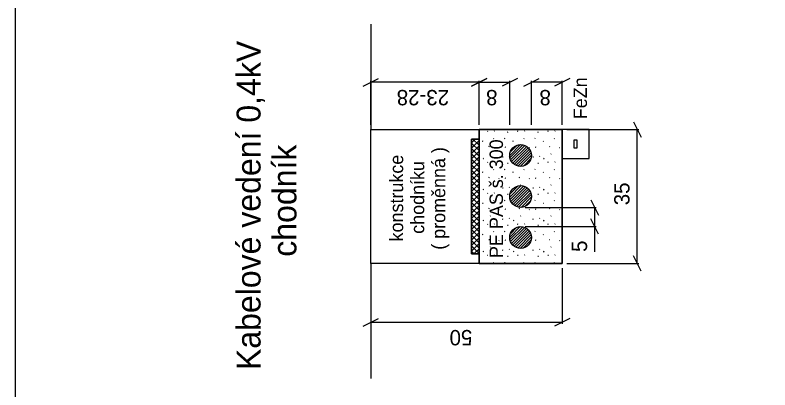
# Model space of a CAD drawing. Extents: x -762592 to -762444, y -1032635 to -1032425.
# Drawn here: x -762592.03 to -762560.49, y -1032580.78 to -1032565.13 of the extents above; entities that cross this region are included whole.
import ezdxf

# ---------------------------------------------------------------- set-up
doc = ezdxf.new("R2010")
doc.units = 0
for name, color, linetype in [('Chráničky - koruflex', 7, 'Continuous'), ('Kabeláž - kabelové vedení HDV - stávající', 7, 'Continuous'), ('Tisk', 7, 'Continuous'), ('X ŘEZY TRASOU', 7, 'Continuous'), ('X ŘEZY TRASOU - KÓTY', 7, 'Continuous'), ('X ŘEZY TRASOU - ŠRAFY', 7, 'Continuous')]:
    doc.layers.add(name, color=color, linetype=linetype)

msp = doc.modelspace()

# ---------------------------------------------------------------- linework, layer by layer
at = {"layer": 'Kabeláž - kabelové vedení HDV - stávající'}
for p, q in [((-762571.36, -1032570.986), (-762570.911, -1032570.538)), ((-762571.349, -1032571.089), (-762570.809, -1032570.548)), ((-762571.336, -1032570.85), (-762571.048, -1032570.562)), ((-762571.323, -1032571.175), (-762570.723, -1032570.576)), ((-762571.282, -1032571.248), (-762570.65, -1032570.616)), ((-762571.231, -1032571.31), (-762570.588, -1032570.667)), ((-762571.171, -1032571.363), (-762570.535, -1032570.728)), ((-762571.099, -1032571.405), (-762570.493, -1032570.798)), ((-762571.016, -1032571.435), (-762570.463, -1032570.882)), ((-762570.917, -1032571.448), (-762570.45, -1032570.981)), ((-762570.789, -1032571.433), (-762570.465, -1032571.109)), ((-762571.359, -1032572.729), (-762570.881, -1032572.25)), ((-762571.349, -1032572.605), (-762571.005, -1032572.262)), ((-762571.344, -1032572.826), (-762570.784, -1032572.267)), ((-762571.312, -1032572.908), (-762570.702, -1032572.297)), ((-762571.269, -1032572.978), (-762570.632, -1032572.341)), ((-762571.216, -1032573.038), (-762570.572, -1032572.394)), ((-762571.152, -1032573.087), (-762570.522, -1032572.457)), ((-762571.078, -1032573.126), (-762570.484, -1032572.532)), ((-762570.991, -1032573.152), (-762570.457, -1032572.618)), ((-762570.886, -1032573.161), (-762570.45, -1032572.724)), ((-762570.743, -1032573.131), (-762570.478, -1032572.866)), ((-762571.36, -1032574.4), (-762570.921, -1032573.962)), ((-762571.352, -1032574.506), (-762570.817, -1032573.971)), ((-762571.332, -1032574.259), (-762571.064, -1032573.991)), ((-762571.325, -1032574.592), (-762570.73, -1032573.997)), ((-762571.286, -1032574.666), (-762570.656, -1032574.036)), ((-762571.236, -1032574.729), (-762570.592, -1032574.085)), ((-762571.176, -1032574.782), (-762570.54, -1032574.146)), ((-762571.107, -1032574.826), (-762570.497, -1032574.216)), ((-762571.024, -1032574.857), (-762570.465, -1032574.298)), ((-762570.927, -1032574.873), (-762570.45, -1032574.396)), ((-762570.802, -1032574.861), (-762570.461, -1032574.52))]:
    msp.add_line(p, q, dxfattribs=at)
at = {"layer": 'Tisk'}
msp.add_lwpolyline([(-762589.528, -1032529.685), (-762592.028, -1032529.685), (-762592.028, -1032634.685), (-762443.528, -1032634.685), (-762443.528, -1032529.685), (-762446.028, -1032529.685)], dxfattribs=at)
at = {"layer": 'X ŘEZY TRASOU'}
for p, q in [((-762577.169, -1032565.505), (-762577.169, -1032569.905)), ((-762572.641, -1032569.905), (-762572.641, -1032575.505)), ((-762572.961, -1032570.459), (-762572.807, -1032570.305)), ((-762572.961, -1032570.685), (-762572.641, -1032570.365)), ((-762572.641, -1032570.791), (-762572.961, -1032570.471)), ((-762572.641, -1032570.564), (-762572.9, -1032570.305)), ((-762572.641, -1032570.338), (-762572.673, -1032570.305)), ((-762572.961, -1032570.912), (-762572.641, -1032570.592)), ((-762572.641, -1032571.017), (-762572.961, -1032570.697)), ((-762572.961, -1032571.138), (-762572.641, -1032570.818)), ((-762572.641, -1032571.243), (-762572.961, -1032570.923)), ((-762572.961, -1032571.364), (-762572.641, -1032571.044)), ((-762572.641, -1032571.47), (-762572.961, -1032571.15)), ((-762572.961, -1032571.59), (-762572.641, -1032571.27)), ((-762572.641, -1032571.696), (-762572.961, -1032571.376)), ((-762572.961, -1032571.817), (-762572.641, -1032571.497)), ((-762572.641, -1032571.922), (-762572.961, -1032571.602)), ((-762572.961, -1032572.043), (-762572.641, -1032571.723)), ((-762572.641, -1032572.148), (-762572.961, -1032571.828)), ((-762572.961, -1032572.269), (-762572.641, -1032571.949)), ((-762572.641, -1032572.375), (-762572.961, -1032572.055)), ((-762572.961, -1032572.495), (-762572.641, -1032572.175)), ((-762572.641, -1032572.601), (-762572.961, -1032572.281)), ((-762572.961, -1032572.722), (-762572.641, -1032572.402)), ((-762572.641, -1032572.827), (-762572.961, -1032572.507)), ((-762572.961, -1032572.948), (-762572.641, -1032572.628)), ((-762572.641, -1032573.053), (-762572.961, -1032572.733)), ((-762572.961, -1032573.174), (-762572.641, -1032572.854)), ((-762572.641, -1032573.28), (-762572.961, -1032572.96)), ((-762572.961, -1032573.401), (-762572.641, -1032573.081)), ((-762572.641, -1032573.506), (-762572.961, -1032573.186)), ((-762572.961, -1032573.627), (-762572.641, -1032573.307)), ((-762572.641, -1032573.732), (-762572.961, -1032573.412)), ((-762572.961, -1032573.853), (-762572.641, -1032573.533)), ((-762572.641, -1032573.959), (-762572.961, -1032573.639)), ((-762572.961, -1032574.079), (-762572.641, -1032573.759)), ((-762572.641, -1032574.185), (-762572.961, -1032573.865)), ((-762572.961, -1032574.306), (-762572.641, -1032573.986)), ((-762572.641, -1032574.411), (-762572.961, -1032574.091)), ((-762572.961, -1032574.532), (-762572.641, -1032574.212)), ((-762572.641, -1032574.637), (-762572.961, -1032574.317)), ((-762572.961, -1032574.758), (-762572.641, -1032574.438)), ((-762572.641, -1032574.864), (-762572.961, -1032574.544)), ((-762572.961, -1032574.984), (-762572.641, -1032574.664)), ((-762572.641, -1032575.09), (-762572.961, -1032574.77)), ((-762572.855, -1032575.105), (-762572.641, -1032574.891)), ((-762572.851, -1032575.105), (-762572.961, -1032574.996)), ((-762577.169, -1032575.505), (-762577.169, -1032580.305)), ((-762577.169, -1032577.105), (-762577.169, -1032579.4))]:
    msp.add_line(p, q, dxfattribs=at)
for points in [[(-762577.169, -1032575.505), (-762577.169, -1032569.905), (-762572.641, -1032569.905), (-762572.641, -1032575.505)], [(-762572.641, -1032575.505), (-762572.641, -1032569.905), (-762569.169, -1032569.905), (-762569.169, -1032575.505)], [(-762569.169, -1032569.905), (-762569.169, -1032571.115), (-762568.047, -1032571.115), (-762568.047, -1032569.905)], [(-762572.961, -1032575.105), (-762572.961, -1032570.305), (-762572.641, -1032570.305), (-762572.641, -1032575.105)], [(-762568.663, -1032570.681), (-762568.663, -1032570.339), (-762568.552, -1032570.339), (-762568.552, -1032570.681)]]:
    msp.add_lwpolyline(points, close=True, dxfattribs=at)
msp.add_lwpolyline([(-762572.641, -1032575.105), (-762572.641, -1032570.305), (-762572.961, -1032570.305), (-762572.961, -1032575.105), (-762572.641, -1032575.105)], dxfattribs=at)
for centre in [(-762570.905, -1032570.993), (-762570.905, -1032572.705), (-762570.905, -1032574.417)]:
    msp.add_circle(centre, 0.456, dxfattribs=at)
at = {"layer": 'X ŘEZY TRASOU - KÓTY'}
for p, q in [((-762577.489, -1032568.096), (-762576.849, -1032567.776)), ((-762577.169, -1032569.713), (-762577.169, -1032567.872)), ((-762572.641, -1032567.936), (-762577.169, -1032567.936)), ((-762572.961, -1032568.096), (-762572.321, -1032567.776)), ((-762572.321, -1032567.776), (-762572.961, -1032568.096)), ((-762572.641, -1032569.713), (-762572.641, -1032567.872)), ((-762572.641, -1032569.713), (-762572.641, -1032567.872)), ((-762572.641, -1032567.936), (-762571.361, -1032567.936)), ((-762571.041, -1032567.776), (-762571.681, -1032568.096)), ((-762571.361, -1032569.713), (-762571.361, -1032567.872)), ((-762570.769, -1032568.096), (-762570.129, -1032567.776)), ((-762570.449, -1032569.713), (-762570.449, -1032567.872)), ((-762569.169, -1032567.936), (-762570.449, -1032567.936)), ((-762568.849, -1032567.776), (-762569.489, -1032568.096)), ((-762569.169, -1032569.713), (-762569.169, -1032567.872)), ((-762566.194, -1032569.585), (-762565.874, -1032570.225)), ((-762568.977, -1032569.905), (-762565.97, -1032569.905)), ((-762566.034, -1032575.505), (-762566.034, -1032569.905)), ((-762567.967, -1032572.841), (-762567.647, -1032573.481)), ((-762570.713, -1032573.161), (-762567.743, -1032573.161)), ((-762567.807, -1032573.961), (-762567.807, -1032573.161)), ((-762567.647, -1032574.281), (-762567.967, -1032573.641)), ((-762570.713, -1032573.961), (-762567.743, -1032573.961)), ((-762567.807, -1032575.022), (-762567.807, -1032573.961)), ((-762565.874, -1032575.825), (-762566.194, -1032575.185)), ((-762568.977, -1032575.505), (-762565.97, -1032575.505)), ((-762577.169, -1032575.697), (-762577.169, -1032578.026)), ((-762569.169, -1032575.697), (-762569.169, -1032578.026)), ((-762577.489, -1032578.122), (-762576.849, -1032577.802)), ((-762568.849, -1032577.802), (-762569.489, -1032578.122)), ((-762569.169, -1032577.962), (-762577.169, -1032577.962))]:
    msp.add_line(p, q, dxfattribs=at)
at = {"layer": 'X ŘEZY TRASOU - ŠRAFY'}
for p, q in [((-762569.169, -1032569.905), (-762572.641, -1032569.905)), ((-762572.641, -1032569.905), (-762572.641, -1032570.305)), ((-762569.169, -1032571.115), (-762569.169, -1032569.905)), ((-762572.271, -1032569.987), (-762572.295, -1032569.976)), ((-762572.006, -1032569.971), (-762571.99, -1032569.96)), ((-762571.453, -1032570.012), (-762571.429, -1032570.01)), ((-762571.006, -1032569.987), (-762571.031, -1032569.976)), ((-762570.741, -1032569.971), (-762570.725, -1032569.96)), ((-762570.188, -1032570.012), (-762570.164, -1032570.01)), ((-762569.742, -1032569.987), (-762569.766, -1032569.976)), ((-762569.477, -1032569.971), (-762569.461, -1032569.96)), ((-762572.641, -1032570.305), (-762572.641, -1032575.105)), ((-762572.472, -1032570.41), (-762572.496, -1032570.399)), ((-762572.035, -1032570.29), (-762572.019, -1032570.28)), ((-762571.573, -1032570.28), (-762571.557, -1032570.269)), ((-762571.207, -1032570.41), (-762571.231, -1032570.399)), ((-762570.771, -1032570.29), (-762570.754, -1032570.28)), ((-762570.309, -1032570.28), (-762570.293, -1032570.269)), ((-762569.942, -1032570.41), (-762569.967, -1032570.399)), ((-762569.506, -1032570.29), (-762569.49, -1032570.28)), ((-762572.208, -1032570.629), (-762572.233, -1032570.618)), ((-762571.814, -1032570.665), (-762571.797, -1032570.654)), ((-762571.521, -1032570.656), (-762571.545, -1032570.645)), ((-762570.549, -1032570.665), (-762570.533, -1032570.654)), ((-762570.256, -1032570.656), (-762570.281, -1032570.645)), ((-762569.679, -1032570.629), (-762569.704, -1032570.618)), ((-762569.285, -1032570.665), (-762569.268, -1032570.654)), ((-762572.641, -1032571.024), (-762572.63, -1032571.017)), ((-762572.471, -1032571.125), (-762572.455, -1032571.114)), ((-762572.465, -1032571.113), (-762572.449, -1032571.102)), ((-762572.177, -1032570.932), (-762572.161, -1032570.921)), ((-762571.632, -1032571.067), (-762571.656, -1032571.056)), ((-762571.381, -1032571.028), (-762571.365, -1032571.017)), ((-762570.367, -1032571.067), (-762570.392, -1032571.056)), ((-762570.117, -1032571.028), (-762570.1, -1032571.017)), ((-762569.942, -1032571.125), (-762569.926, -1032571.114)), ((-762569.936, -1032571.113), (-762569.92, -1032571.102)), ((-762569.648, -1032570.932), (-762569.631, -1032570.921)), ((-762572.271, -1032571.284), (-762572.295, -1032571.273)), ((-762572.006, -1032571.268), (-762571.99, -1032571.257)), ((-762571.453, -1032571.309), (-762571.429, -1032571.307)), ((-762570.188, -1032571.309), (-762570.164, -1032571.307)), ((-762569.742, -1032571.284), (-762569.766, -1032571.273)), ((-762569.477, -1032571.268), (-762569.461, -1032571.257)), ((-762572.472, -1032571.707), (-762572.496, -1032571.696)), ((-762572.035, -1032571.587), (-762572.019, -1032571.577)), ((-762571.573, -1032571.577), (-762571.557, -1032571.566)), ((-762571.207, -1032571.707), (-762571.231, -1032571.696)), ((-762570.771, -1032571.587), (-762570.754, -1032571.577)), ((-762570.309, -1032571.577), (-762570.293, -1032571.566)), ((-762569.942, -1032571.707), (-762569.967, -1032571.696)), ((-762569.506, -1032571.587), (-762569.49, -1032571.577)), ((-762572.208, -1032571.926), (-762572.233, -1032571.915)), ((-762571.814, -1032571.962), (-762571.797, -1032571.951)), ((-762571.521, -1032571.953), (-762571.545, -1032571.942)), ((-762570.944, -1032571.926), (-762570.968, -1032571.915)), ((-762570.549, -1032571.962), (-762570.533, -1032571.951)), ((-762570.256, -1032571.953), (-762570.281, -1032571.942)), ((-762569.679, -1032571.926), (-762569.704, -1032571.915)), ((-762569.285, -1032571.962), (-762569.268, -1032571.951)), ((-762572.641, -1032572.321), (-762572.63, -1032572.314)), ((-762572.471, -1032572.422), (-762572.455, -1032572.411)), ((-762572.465, -1032572.41), (-762572.449, -1032572.399)), ((-762572.177, -1032572.229), (-762572.161, -1032572.218)), ((-762571.632, -1032572.364), (-762571.656, -1032572.353)), ((-762571.381, -1032572.325), (-762571.365, -1032572.314)), ((-762570.912, -1032572.229), (-762570.896, -1032572.218)), ((-762570.367, -1032572.364), (-762570.392, -1032572.353)), ((-762570.117, -1032572.325), (-762570.1, -1032572.314)), ((-762569.942, -1032572.422), (-762569.926, -1032572.411)), ((-762569.936, -1032572.41), (-762569.92, -1032572.399)), ((-762569.648, -1032572.229), (-762569.631, -1032572.218)), ((-762572.271, -1032572.581), (-762572.295, -1032572.57)), ((-762572.006, -1032572.565), (-762571.99, -1032572.554)), ((-762571.453, -1032572.606), (-762571.429, -1032572.604)), ((-762570.188, -1032572.606), (-762570.164, -1032572.604)), ((-762569.742, -1032572.581), (-762569.766, -1032572.57)), ((-762569.477, -1032572.565), (-762569.461, -1032572.554)), ((-762572.472, -1032573.003), (-762572.496, -1032572.993)), ((-762572.035, -1032572.884), (-762572.019, -1032572.874)), ((-762571.573, -1032572.874), (-762571.557, -1032572.863)), ((-762570.309, -1032572.874), (-762570.293, -1032572.863)), ((-762569.942, -1032573.003), (-762569.967, -1032572.993)), ((-762569.506, -1032572.884), (-762569.49, -1032572.874)), ((-762572.208, -1032573.223), (-762572.233, -1032573.212)), ((-762571.814, -1032573.259), (-762571.797, -1032573.248)), ((-762571.521, -1032573.25), (-762571.545, -1032573.239)), ((-762570.944, -1032573.223), (-762570.968, -1032573.212)), ((-762570.549, -1032573.259), (-762570.533, -1032573.248)), ((-762570.256, -1032573.25), (-762570.281, -1032573.239)), ((-762569.679, -1032573.223), (-762569.704, -1032573.212)), ((-762569.285, -1032573.259), (-762569.268, -1032573.248)), ((-762572.641, -1032573.618), (-762572.63, -1032573.611)), ((-762572.471, -1032573.718), (-762572.455, -1032573.708)), ((-762572.465, -1032573.707), (-762572.449, -1032573.696)), ((-762572.177, -1032573.526), (-762572.161, -1032573.515)), ((-762571.632, -1032573.661), (-762571.656, -1032573.65)), ((-762571.381, -1032573.622), (-762571.365, -1032573.611)), ((-762571.207, -1032573.718), (-762571.191, -1032573.708)), ((-762571.201, -1032573.707), (-762571.184, -1032573.696)), ((-762570.912, -1032573.526), (-762570.896, -1032573.515)), ((-762570.367, -1032573.661), (-762570.392, -1032573.65)), ((-762570.117, -1032573.622), (-762570.1, -1032573.611)), ((-762569.942, -1032573.718), (-762569.926, -1032573.708)), ((-762569.936, -1032573.707), (-762569.92, -1032573.696)), ((-762569.648, -1032573.526), (-762569.631, -1032573.515)), ((-762572.271, -1032573.878), (-762572.295, -1032573.867)), ((-762572.006, -1032573.861), (-762571.99, -1032573.851)), ((-762571.453, -1032573.903), (-762571.429, -1032573.901)), ((-762571.006, -1032573.878), (-762571.031, -1032573.867)), ((-762570.741, -1032573.861), (-762570.725, -1032573.851)), ((-762570.188, -1032573.903), (-762570.164, -1032573.901)), ((-762569.742, -1032573.878), (-762569.766, -1032573.867)), ((-762569.477, -1032573.861), (-762569.461, -1032573.851)), ((-762572.472, -1032574.3), (-762572.496, -1032574.29)), ((-762572.035, -1032574.181), (-762572.019, -1032574.171)), ((-762571.573, -1032574.171), (-762571.557, -1032574.16)), ((-762570.309, -1032574.171), (-762570.293, -1032574.16)), ((-762569.942, -1032574.3), (-762569.967, -1032574.29)), ((-762569.506, -1032574.181), (-762569.49, -1032574.171)), ((-762572.208, -1032574.52), (-762572.233, -1032574.509)), ((-762571.814, -1032574.556), (-762571.797, -1032574.545)), ((-762571.521, -1032574.547), (-762571.545, -1032574.536)), ((-762570.256, -1032574.547), (-762570.281, -1032574.536)), ((-762569.679, -1032574.52), (-762569.704, -1032574.509)), ((-762569.285, -1032574.556), (-762569.268, -1032574.545)), ((-762572.641, -1032574.915), (-762572.63, -1032574.908)), ((-762572.177, -1032574.823), (-762572.161, -1032574.812)), ((-762571.632, -1032574.958), (-762571.656, -1032574.947)), ((-762571.381, -1032574.919), (-762571.365, -1032574.908)), ((-762570.367, -1032574.958), (-762570.392, -1032574.947)), ((-762570.117, -1032574.919), (-762570.1, -1032574.908)), ((-762569.648, -1032574.823), (-762569.631, -1032574.812)), ((-762572.471, -1032575.015), (-762572.455, -1032575.005)), ((-762572.465, -1032575.004), (-762572.449, -1032574.993)), ((-762572.271, -1032575.175), (-762572.295, -1032575.164)), ((-762572.006, -1032575.158), (-762571.99, -1032575.148)), ((-762571.453, -1032575.2), (-762571.429, -1032575.197)), ((-762571.207, -1032575.015), (-762571.191, -1032575.005)), ((-762571.201, -1032575.004), (-762571.184, -1032574.993)), ((-762571.006, -1032575.175), (-762571.031, -1032575.164)), ((-762570.741, -1032575.158), (-762570.725, -1032575.148)), ((-762570.188, -1032575.2), (-762570.164, -1032575.197)), ((-762569.942, -1032575.015), (-762569.926, -1032575.005)), ((-762569.936, -1032575.004), (-762569.92, -1032574.993)), ((-762569.742, -1032575.175), (-762569.766, -1032575.164)), ((-762569.477, -1032575.158), (-762569.461, -1032575.148)), ((-762572.035, -1032575.478), (-762572.019, -1032575.467)), ((-762571.573, -1032575.468), (-762571.557, -1032575.457)), ((-762570.771, -1032575.478), (-762570.754, -1032575.467)), ((-762570.309, -1032575.468), (-762570.293, -1032575.457)), ((-762569.506, -1032575.478), (-762569.49, -1032575.467))]:
    msp.add_line(p, q, dxfattribs=at)
msp.add_lwpolyline([(-762572.641, -1032575.105), (-762572.641, -1032575.505), (-762569.169, -1032575.505), (-762569.169, -1032571.115)], dxfattribs=at)
for centre in [(-762570.905, -1032570.993), (-762570.905, -1032572.705), (-762570.905, -1032574.417)]:
    msp.add_circle(centre, 0.456, dxfattribs=at)

# ---------------------------------------------------------------- texts
at = {"layer": 'Chráničky - koruflex'}
for s, p in [('Kabelové vedení 0,4kV', (-762581.772, -1032579.956)), ('chodník', (-762580.272, -1032575.222))]:
    msp.add_text(s, height=1, rotation=90, dxfattribs=at).set_placement(p)
at = {"layer": 'X ŘEZY TRASOU'}
for s, p in [('FeZn', (-762568.133, -1032569.477)), ('PE PAS š. 300', (-762571.641, -1032575.274)), ('( proměnná )', (-762574.053, -1032574.93)), ('konstrukce', (-762575.813, -1032574.581)), ('chodníku', (-762574.933, -1032574.265))]:
    msp.add_text(s, height=0.56, rotation=90, dxfattribs=at).set_placement(p)
at = {"layer": 'X ŘEZY TRASOU - KÓTY'}
for s, rotation, p in [('23-28', 180, (-762573.892, -1032568.256)), ('8', 180, (-762571.872, -1032568.256)), ('8', 180, (-762569.641, -1032568.256)), ('35', 90, (-762566.354, -1032573.072)), ('5', 90, (-762568.127, -1032575.022)), ('50', 180, (-762572.922, -1032578.282))]:
    msp.add_text(s, height=0.64, rotation=rotation, dxfattribs=at).set_placement(p)

doc.saveas('drawing.dxf')
